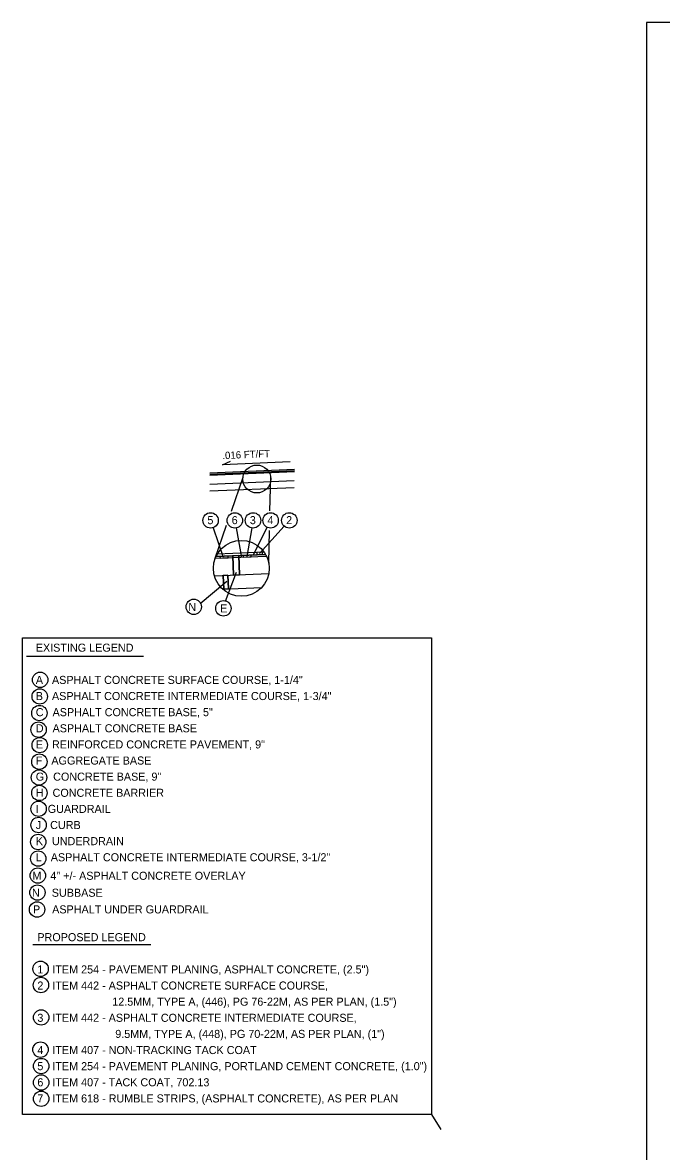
# Model space of a CAD drawing. Extents: x -196 to 300, y -73 to 205.
# Drawn here: x -51.8 to 1.2, y 16.2 to 110 of the extents above; entities that cross this region are included whole.
import ezdxf

# ---------------------------------------------------------------- set-up
doc = ezdxf.new("R2010")
doc.units = 0
for name, color, linetype in [('Level 1', 7, 'Continuous'), ('Level 4', 7, 'Continuous'), ('Level 59', 7, 'Continuous'), ('Level 6', 7, 'Continuous'), ('Level 60', 7, 'Continuous'), ('Level 7', 7, 'Continuous'), ('SH_Cut_Line', 7, 'Continuous')]:
    doc.layers.add(name, color=color, linetype=linetype)

msp = doc.modelspace()

# ---------------------------------------------------------------- linework, layer by layer
at = {"layer": 'Level 1'}
for p, q in [((-35.985, 68.028), (-35.145, 65.581)), ((-34.063, 68.004), (-33.623, 65.558)), ((-32.777, 68.003), (-33.182, 65.635)), ((-31.495, 68.062), (-32.661, 65.758)), ((-30.082, 68.158), (-32.132, 65.882))]:
    msp.add_line(p, q, dxfattribs=at)
at = {"layer": 'Level 4'}
for p, q in [((-35.197, 73.242), (-34.532, 73.562)), ((-29.572, 73.495), (-35.197, 73.242))]:
    msp.add_line(p, q, dxfattribs=at)
at = {"layer": 'Level 59'}
for p, q in [((-34.942, 61.927), (-34.049, 64.336)), ((-37.06, 61.723), (-34.837, 63.576)), ((-51.478, 57.346), (-41.764, 57.346)), ((-50.948, 33.405), (-41.152, 33.405)), ((-17.844, 19.254), (-17.066, 18.032))]:
    msp.add_line(p, q, dxfattribs=at)
for points in [[(-35.404, 65.482), (-34.739, 65.51), (-34.746, 65.67), (-35.411, 65.642)], [(-34.277, 64.095), (-33.793, 64.116), (-33.86, 65.707), (-34.345, 65.687)], [(-33.479, 65.564), (-32.814, 65.592), (-32.82, 65.751), (-33.485, 65.723)], [(-32.342, 65.772), (-31.871, 65.792), (-31.879, 65.991), (-32.351, 65.971)], [(-35.094, 62.928), (-34.716, 62.944), (-34.764, 64.075), (-35.142, 64.059)], [(-51.806, 58.885), (-17.844, 58.885), (-17.844, 19.254), (-51.806, 19.254)]]:
    msp.add_lwpolyline(points, close=True, dxfattribs=at)
for centre in [(-36.193, 68.633), (-34.176, 68.633), (-32.669, 68.633), (-31.206, 68.633), (-29.654, 68.633), (-37.589, 61.452), (-35.131, 61.326), (-50.349, 55.382), (-50.381, 54.003), (-50.413, 52.624), (-50.477, 51.245), (-50.381, 49.962), (-50.413, 48.583), (-50.445, 47.268), (-50.413, 45.985), (-50.477, 44.67), (-50.477, 43.322), (-50.509, 41.911), (-50.509, 40.532), (-50.541, 39.121), (-50.573, 37.71), (-50.605, 36.298), (-50.31, 31.372), (-50.284, 30.025), (-50.265, 27.331), (-50.316, 24.655), (-50.265, 23.293), (-50.265, 21.927), (-50.265, 20.574)]:
    msp.add_circle(centre, 0.639, dxfattribs=at)
at = {"layer": 'Level 6'}
for p, q in [((-36.268, 72.473), (-29.223, 72.772)), ((-36.268, 71.642), (-29.241, 71.94)), ((-36.268, 71.076), (-29.253, 71.373)), ((-35.744, 65.628), (-31.623, 65.802)), ((-35.875, 64.028), (-31.357, 64.219)), ((-35.191, 62.924), (-31.946, 63.062))]:
    msp.add_line(p, q, dxfattribs=at)
at = {"layer": 'Level 60'}
for points in [[(-34.277, 64.095), (-34.345, 65.687), (-33.86, 65.707), (-33.793, 64.116)], [(-35.094, 62.928), (-35.141, 64.059), (-34.764, 64.075), (-34.716, 62.944)]]:
    msp.add_lwpolyline(points, close=True, dxfattribs=at)
at = {"layer": 'Level 7'}
for p, q in [((-36.268, 72.598), (-29.22, 72.897)), ((-36.268, 72.473), (-29.223, 72.772)), ((-36.268, 72.39), (-29.225, 72.688)), ((-34.466, 69.41), (-33.5, 72.237)), ((-31.261, 69.42), (-31.2, 72.219)), ((-35.834, 65.404), (-34.865, 68.241)), ((-31.356, 65.073), (-31.296, 67.799)), ((-31.623, 65.802), (-35.744, 65.628)), ((-31.747, 65.997), (-35.637, 65.832)), ((-31.541, 65.646), (-35.812, 65.465))]:
    msp.add_line(p, q, dxfattribs=at)
for centre, radius in [((-32.351, 72.072), 1.161), ((-33.638, 64.65), 2.322)]:
    msp.add_circle(centre, radius, dxfattribs=at)
at = {"layer": 'SH_Cut_Line'}
msp.add_lwpolyline([(0, 0), (170, 0), (170, 110), (0, 110)], close=True, dxfattribs=at)

# ---------------------------------------------------------------- texts
at = {"layer": 'Level 4'}
msp.add_text('.016 FT/FT', height=0.6, rotation=2.57074, dxfattribs=at).set_placement((-35.206, 73.719))
at = {"layer": 'Level 59'}
for s, height, p in [('5', 0.67, (-36.457, 68.32)), ('6', 0.67, (-34.44, 68.32)), ('3', 0.67, (-32.933, 68.32)), ('4', 0.67, (-31.47, 68.32)), ('2', 0.67, (-29.918, 68.32)), ('N', 0.67, (-38.038, 61.101)), ('E', 0.67, (-35.39, 60.987)), ('EXISTING LEGEND', 0.66984, (-50.71, 57.722)), ('A   ASPHALT CONCRETE SURFACE COURSE, 1-1/4"', 0.66984, (-50.71, 55.043)), ('B   ASPHALT CONCRETE INTERMEDIATE COURSE, 1-3/4"', 0.66984, (-50.71, 53.703)), ('C   ASPHALT CONCRETE BASE, 5"', 0.66984, (-50.71, 52.363)), ('D   ASPHALT CONCRETE BASE', 0.66984, (-50.71, 51.024)), ('E   REINFORCED CONCRETE PAVEMENT, 9"', 0.66984, (-50.71, 49.684)), ('F   AGGREGATE BASE', 0.66984, (-50.71, 48.344)), ('G   CONCRETE BASE, 9"', 0.66984, (-50.71, 47.005)), ('H   CONCRETE BARRIER', 0.66984, (-50.71, 45.665)), ('I   GUARDRAIL ', 0.66984, (-50.71, 44.325)), ('J   CURB', 0.6698, (-50.71, 42.986)), ('K   UNDERDRAIN ', 0.66984, (-50.71, 41.646)), ('L   ASPHALT CONCRETE INTERMEDIATE COURSE, 3-1/2"          ', 0.66984, (-50.71, 40.306)), ('M   4" +/- ASPHALT CONCRETE OVERLAY   ', 0.66984, (-50.991, 38.769)), ('N    SUBBASE', 0.66984, (-51.023, 37.358)), ('P    ASPHALT UNDER GUARDRAIL', 0.66984, (-50.943, 35.975)), ('PROPOSED LEGEND', 0.66984, (-50.58, 33.665)), ('1   ITEM 254 - PAVEMENT PLANING, ASPHALT CONCRETE, (2.5")', 0.66984, (-50.58, 30.986)), ('2   ITEM 442 - ASPHALT CONCRETE SURFACE COURSE,', 0.66984, (-50.58, 29.646)), ('                         12.5MM, TYPE A, (446), PG 76-22M, AS PER PLAN, (1.5")', 0.66984, (-50.58, 28.306)), ('3   ITEM 442 - ASPHALT CONCRETE INTERMEDIATE COURSE,', 0.66984, (-50.58, 26.967)), ('                          9.5MM, TYPE A, (448), PG 70-22M, AS PER PLAN, (1")', 0.66984, (-50.58, 25.627)), ('4   ITEM 407 - NON-TRACKING TACK COAT', 0.66984, (-50.58, 24.287)), ('5   ITEM 254 - PAVEMENT PLANING, PORTLAND CEMENT CONCRETE, (1.0")', 0.66984, (-50.58, 22.948)), ('6   ITEM 407 - TACK COAT, 702.13', 0.66984, (-50.58, 21.608)), ('7   ITEM 618 - RUMBLE STRIPS, (ASPHALT CONCRETE), AS PER PLAN', 0.66984, (-50.58, 20.268))]:
    msp.add_text(s, height=height, dxfattribs=at).set_placement(p)

doc.saveas('drawing.dxf')
